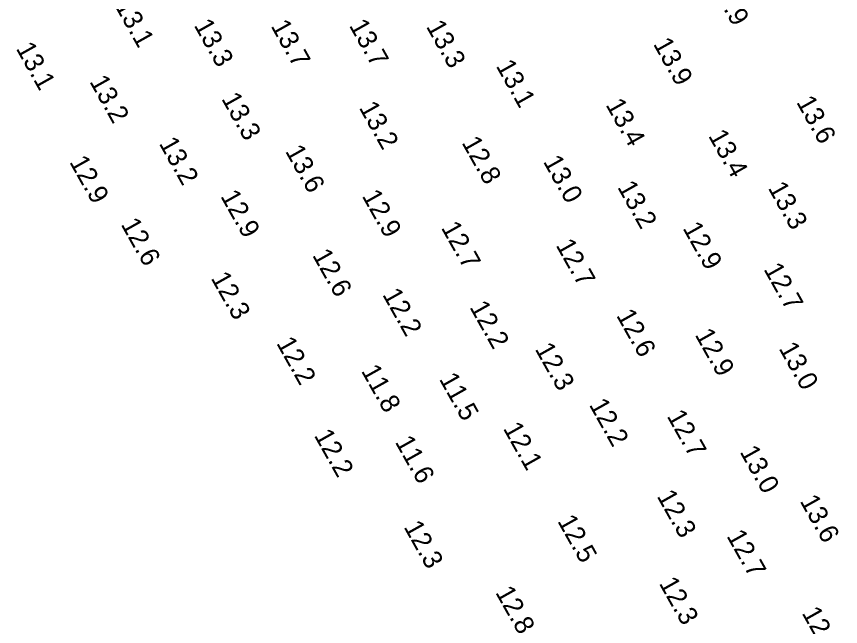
# Model space of a CAD drawing. Extents: x 1023796 to 1112670, y 656573 to 837340.
# Drawn here: x 1109030.2 to 1109245.3, y 682247.1 to 682406.3 of the extents above; entities that cross this region are included whole.
import ezdxf

# ---------------------------------------------------------------- set-up
doc = ezdxf.new("R2010")
doc.units = 0
doc.layers.add('V-TOPO-SOUN', color=7, linetype='Continuous')

msp = doc.modelspace()

# ---------------------------------------------------------------- texts
at = {"layer": 'V-TOPO-SOUN'}
for s, p in [('13.9 ', (1109211.04, 682414.81)), ('13.1 ', (1109055.71, 682409.16)), ('13.3 ', (1109076.39, 682404.05)), ('13.7 ', (1109096.47, 682403.86)), ('13.7 ', (1109116.91, 682403.99)), ('13.3 ', (1109137.02, 682403.73)), ('13.9 ', (1109196.31, 682399.17)), ('13.1 ', (1109029.92, 682398)), ('13.1 ', (1109155.25, 682393.44)), ('13.2 ', (1109049.13, 682389.36)), ('13.3 ', (1109083.58, 682384.86)), ('13.4 ', (1109183.91, 682383.29)), ('13.6 ', (1109233.69, 682383.98)), ('13.2 ', (1109119.5, 682382.53)), ('13.4 ', (1109210.71, 682375.18)), ('13.2 ', (1109067.27, 682373.21)), ('12.8 ', (1109146.31, 682373.41)), ('13.6 ', (1109100.23, 682371.18)), ('12.9 ', (1109043.88, 682368.36)), ('13.0 ', (1109167.58, 682368.47)), ('13.2 ', (1109186.96, 682361.8)), ('13.3 ', (1109226.29, 682361.57)), ('12.9 ', (1109083.32, 682359.43)), ('12.9 ', (1109120.26, 682359.5)), ('12.6 ', (1109057.31, 682352.09)), ('12.7 ', (1109140.93, 682351.2)), ('12.9 ', (1109204.02, 682351.07)), ('12.7 ', (1109170.88, 682346.64)), ('12.6 ', (1109107.31, 682344.02)), ('12.7 ', (1109225.15, 682340.37)), ('12.3 ', (1109080.82, 682338.04)), ('12.2 ', (1109125.61, 682333.75)), ('12.2 ', (1109148.37, 682330.46)), ('12.6 ', (1109186.68, 682328.3)), ('12.9 ', (1109207.2, 682323.25)), ('12.2 ', (1109097.92, 682321.05)), ('12.3 ', (1109165.43, 682319.54)), ('13.0 ', (1109229.12, 682319.69)), ('11.8 ', (1109120.06, 682313.83)), ('11.5 ', (1109140.43, 682311.68)), ('12.2 ', (1109179.58, 682304.97)), ('12.7 ', (1109199.88, 682302.02)), ('12.1 ', (1109157.12, 682298.79)), ('12.2 ', (1109107.76, 682296.97)), ('11.6 ', (1109128.9, 682295.26)), ('13.0 ', (1109218.92, 682292.69)), ('12.3 ', (1109197.26, 682281.12)), ('13.6 ', (1109234.61, 682279.84)), ('12.5 ', (1109171.31, 682274.6)), ('12.3 ', (1109131.18, 682273.08)), ('12.7 ', (1109215.47, 682270.72)), ('12.3 ', (1109197.82, 682258.38)), ('12.8 ', (1109155.1, 682255.99)), ('12.8 ', (1109235.12, 682250.61))]:
    msp.add_text(s, height=5, rotation=299.3001, dxfattribs=at).set_placement(p)

doc.saveas('drawing.dxf')
